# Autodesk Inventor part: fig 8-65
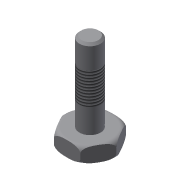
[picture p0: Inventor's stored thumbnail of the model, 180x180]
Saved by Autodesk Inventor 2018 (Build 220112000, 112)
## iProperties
Shininess: 77.0
Length Units: 11269
Angle Units: 11279
Time Units: 11290
Mass Units: 11283
Length Display Precision: 3
Angle Display Precision: 2
Created: 2002-01
Part Number: fig 8-65
Document SubType Name: Modeling
Designer: ***
Density: 1 g/cm^3
Material: Generic
Appearance: Default
Density: 0.0
Volumn: 0.0
Area: 0.0
PropertySet Name: Model Information
Control State: 0
Master: False
Checked Out: False
Author: ***
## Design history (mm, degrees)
sketch "Sketch1"
  geometry: C1 r 25 at (0, 0)
  constraints: 1 centre point
  dimensions: "d0" = 50 diameter of C1
extrude "Extrusion1" new body sketch "Sketch1" distance "d1" = 15; taper "d2" = 0 deg
fillet "Fillet1" dims "d3" = 5
sketch "Sketch2"
  geometry: L1 (25.058, 0)-(12.529, -21.701); L2 (12.529, -21.701)-(-12.529, -21.701); L3 (-12.529, -21.701)-(-25.058, 0); L4 (-25.058, 0)-(-12.529, 21.701); L5 (-12.529, 21.701)-(12.529, 21.701); L6 (12.529, 21.701)-(25.058, 0); 1 further point
  constraints: 12 end point, 11 other
extrude "Extrusion2" sketch "Sketch2" extent not by distance; stored distance "d4" = 15; taper "d5" = 0 deg
sketch "Sketch3"
  geometry: C1 r 10.044 at (0, 0); 1 further point
  constraints: 1 centre point, 1 coincident
extrude "Extrusion3" join sketch "Sketch3" distance "d6" = 75; taper "d7" = 0 deg
chamfer "Chamfer1" distance "d8" = 2; stored, may be unused: second distance "d9" = 2, angle "d16" = 45 deg
thread "Thread3" dims "d14" = 30, "d15" = 20
body "Solid1"
